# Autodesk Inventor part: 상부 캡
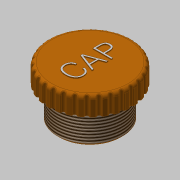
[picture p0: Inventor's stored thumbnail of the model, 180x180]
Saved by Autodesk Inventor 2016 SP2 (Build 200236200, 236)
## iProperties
Created: 2016-09
Part Number: 상부 캡
Material: ABS 플라스틱
Document SubType Name: Modeling
Designer: mduedu
Density: 1.06 g/cm^3
Mass: 28.3049 g
Surface Area: 72.7426 cm^2
Volume: 26.7028 cm^3
Appearance: 주황색
Author: mduedu
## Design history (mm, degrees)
sketch "스케치1"
  geometry: C1 r 22.5 at (0, 0); 1 further point
  constraints: 1 centre point, 1 coincident
  dimensions: "d0" = 45 diameter of C1
extrude "돌출1" new body sketch "스케치1" distance "d1" = 10; taper "d2" = 0 deg
fillet "모깎기1" dims "d11" = 2
sketch "스케치4"
  geometry: C1 r 17.5 at (0, 0); 1 further point
  constraints: 1 centre point, 1 coincident
  dimensions: "d14" = 35 diameter of C1
extrude "돌출4" join sketch "스케치4" distance "d15" = 17; taper "d16" = 0 deg
sketch "스케치5"
  geometry: C1 r 12.5 at (0, 0); 1 further point
  constraints: 1 centre point, 1 coincident
  dimensions: "d17" = 25 diameter of C1
extrude "돌출5" cut sketch "스케치5" distance "d18" = 10; taper "d19" = 0 deg
fillet "모깎기4" dims "d20" = 3
sketch "스케치6"
  geometry: L1 (0, 22.5)-(0, -22.5) reference; L2 (0, 17.5)-(-1, 17.5); L3 (-1, 17.5)-(-1, 16.5); L4 (-1, 16.5)-(0, 16.5); L5 (0, 16.5)-(0, 17.5); L6 (0, 17.5)-(-17, 17.5) reference; L7 (-20.4, 0)-(3.4, 0) reference; 1 further point
  constraints: 8 end point, 2 parallel, 1 collinear, 1 horizontal, 1 perpendicular, 1 point on line
  dimensions: "d26" = 1 distance of L2.start L2.end; "d28" = 1 distance of L2.end L3.end
revolve "회전1" sketch "스케치6" stored, may be unused: angle "d29" = 90 deg
feature "스레드1" dims "d21" = 10, "d22" = 0
chamfer "모따기1" distance "d23" = 1; stored, may be unused: second distance "d24" = 2, angle "d25" = 45 deg
chamfer "모따기2" distance "d30" = 1; stored, may be unused: second distance "d31" = 2, angle "d32" = 45 deg
sketch "스케치7"
  geometry: C1 r 1 at (0, 22.5); 2 further points
  constraints: 2 vertical alignment, 1 centre point, 1 other
  dimensions: "d33" = 2 diameter of C1
extrude "돌출6" cut sketch "스케치7" stored distance "d35" = 10; taper "d36" = 0 deg
fillet "모깎기5" dims "d37" = 0.5
sketch "스케치8"
  geometry: 2 further points
  constraints: 1 coincident, 1 other
feature "엠보싱1" sketch "스케치8" dims "d0" = 45, "d41" = 0.5, "d42" = 0
node "솔리드1"
pattern_circular "원형 패턴1" dims angle "d39" = 360 deg
